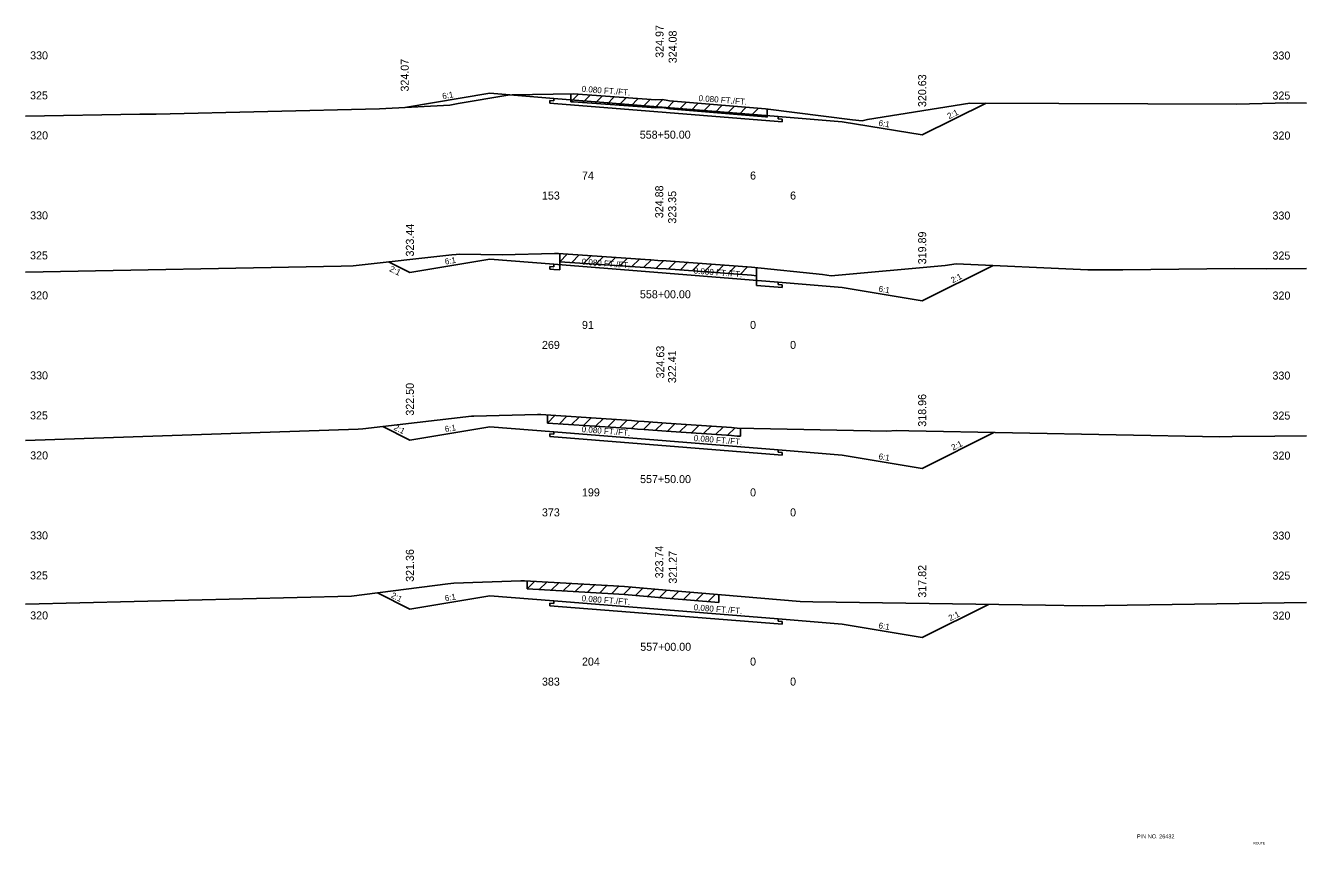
# Model space of a CAD drawing. Extents: x 2967 to 4323, y -3677 to -817.
# Drawn here: x 3555.3 to 3715.3, y -1162.9 to -1060.5 of the extents above; entities that cross this region are included whole.
import ezdxf

# ---------------------------------------------------------------- set-up
doc = ezdxf.new("R2010")
doc.units = 0
for name, color, linetype in [('Level 1', 7, 'Continuous'), ('Level 10', 7, 'Continuous'), ('Level 11', 7, 'Continuous'), ('Level 12', 7, 'Continuous'), ('Level 20', 7, 'Continuous'), ('Level 3', 7, 'Continuous'), ('Level 32', 7, 'Continuous'), ('Level 33', 7, 'Continuous'), ('Level 59', 7, 'Continuous'), ('Level 6', 7, 'Continuous'), ('Level 60', 7, 'Continuous'), ('Level 61', 7, 'Continuous'), ('Level 7', 7, 'Continuous')]:
    doc.layers.add(name, color=color, linetype=linetype)

msp = doc.modelspace()

# ---------------------------------------------------------------- linework, layer by layer
at = {"layer": 'Level 11'}
for p, q in [((3621.35, -1069.94), (3620.85, -1069.9)), ((3620.85, -1069.9), (3620.85, -1070.24)), ((3620.85, -1070.24), (3621.35, -1070.28)), ((3621.35, -1069.64), (3621.35, -1069.94)), ((3649.35, -1072.18), (3649.35, -1071.88)), ((3649.85, -1072.22), (3649.35, -1072.18)), ((3649.35, -1072.52), (3649.85, -1072.56)), ((3649.85, -1072.56), (3649.85, -1072.22)), ((3621.35, -1090.67), (3620.85, -1090.63)), ((3620.85, -1090.63), (3620.85, -1090.97)), ((3620.85, -1090.97), (3621.35, -1091.01)), ((3621.35, -1090.37), (3621.35, -1090.67)), ((3649.35, -1092.91), (3649.35, -1092.61)), ((3649.85, -1092.95), (3649.35, -1092.91)), ((3649.35, -1093.25), (3649.85, -1093.29)), ((3649.85, -1093.29), (3649.85, -1092.95)), ((3621.35, -1111.61), (3620.85, -1111.57)), ((3621.35, -1111.31), (3621.35, -1111.61)), ((3649.35, -1113.85), (3649.35, -1113.55)), ((3649.85, -1113.89), (3649.35, -1113.85)), ((3649.35, -1114.19), (3649.85, -1114.23)), ((3649.85, -1114.23), (3649.85, -1113.89)), ((3621.35, -1132.75), (3620.85, -1132.71)), ((3621.35, -1132.45), (3621.35, -1132.75)), ((3649.35, -1134.99), (3649.35, -1134.69)), ((3649.85, -1135.03), (3649.35, -1134.99)), ((3649.35, -1135.33), (3649.85, -1135.37)), ((3649.85, -1135.37), (3649.85, -1135.03))]:
    msp.add_line(p, q, dxfattribs=at)
at = {"layer": 'Level 12'}
for p, q in [((3635.35, -1071.4), (3621.35, -1070.28)), ((3635.35, -1071.4), (3649.35, -1072.52)), ((3622.08, -1089.05), (3622.08, -1091.07)), ((3622.08, -1091.07), (3621.35, -1091.01)), ((3646.64, -1090.81), (3646.64, -1093.04)), ((3646.64, -1093.04), (3649.35, -1093.25)), ((3620.85, -1111.57), (3620.85, -1111.91)), ((3620.85, -1111.91), (3649.35, -1114.19)), ((3620.85, -1132.71), (3620.85, -1133.05)), ((3620.85, -1133.05), (3649.35, -1135.33))]:
    msp.add_line(p, q, dxfattribs=at)
at = {"layer": 'Level 59'}
for p, q in [((3621.35, -1069.64), (3635.35, -1070.76)), ((3635.35, -1070.76), (3649.35, -1071.88)), ((3621.35, -1090.37), (3635.35, -1091.49)), ((3635.35, -1091.49), (3649.35, -1092.61)), ((3621.35, -1111.31), (3635.35, -1112.43)), ((3635.35, -1112.43), (3649.35, -1113.55)), ((3621.35, -1132.45), (3635.35, -1133.57)), ((3635.35, -1133.57), (3649.35, -1134.69))]:
    msp.add_line(p, q, dxfattribs=at)
at = {"layer": 'Level 6'}
for p, q in [((3613.35, -1069), (3621.35, -1069.64)), ((3649.35, -1071.88), (3657.35, -1072.55)), ((3613.35, -1089.73), (3621.35, -1090.37)), ((3649.35, -1092.61), (3657.35, -1093.28)), ((3613.35, -1110.67), (3621.35, -1111.31)), ((3649.35, -1113.55), (3657.35, -1114.22)), ((3613.35, -1131.81), (3621.35, -1132.45)), ((3649.35, -1134.69), (3657.35, -1135.36))]:
    msp.add_line(p, q, dxfattribs=at)
at = {"layer": 'Level 60'}
for p, q in [((3608.33, -1070.47), (3609.37, -1070.27)), ((3609.37, -1070.27), (3615.57, -1069.25)), ((3615.57, -1069.25), (3616.12, -1069.2)), ((3616.12, -1069.2), (3623.79, -1069.08)), ((3623.79, -1069.08), (3634.08, -1069.83)), ((3634.08, -1069.83), (3634.86, -1069.77)), ((3634.86, -1069.77), (3635.35, -1069.87)), ((3635.35, -1069.87), (3635.78, -1069.96)), ((3635.78, -1069.96), (3647.78, -1070.95)), ((3660.53, -1072.29), (3673.29, -1070.22)), ((3673.29, -1070.22), (3706.65, -1070.35)), ((3706.65, -1070.35), (3713.05, -1070.21)), ((3713.05, -1070.21), (3715.35, -1070.22)), ((3555.35, -1071.87), (3569.62, -1071.6)), ((3569.62, -1071.6), (3571.66, -1071.59)), ((3571.66, -1071.59), (3599.54, -1070.94)), ((3599.54, -1070.94), (3608.33, -1070.47)), ((3647.78, -1070.95), (3658.63, -1072.31)), ((3658.63, -1072.31), (3659.86, -1072.46)), ((3659.86, -1072.46), (3660.53, -1072.29)), ((3596.28, -1090.56), (3608.61, -1089.18)), ((3608.61, -1089.18), (3609.15, -1089.15)), ((3609.15, -1089.15), (3609.54, -1089.09)), ((3609.54, -1089.09), (3614.9, -1089.18)), ((3614.9, -1089.18), (3621.43, -1089.04)), ((3621.43, -1089.04), (3621.9, -1089.03)), ((3621.9, -1089.03), (3632.74, -1089.76)), ((3555.35, -1091.34), (3594.75, -1090.59)), ((3594.75, -1090.59), (3596.28, -1090.56)), ((3632.74, -1089.76), (3633.45, -1089.82)), ((3633.45, -1089.82), (3634.33, -1089.89)), ((3634.33, -1089.89), (3635.35, -1089.96)), ((3635.35, -1089.96), (3646.02, -1090.75)), ((3646.02, -1090.75), (3654.89, -1091.66)), ((3655.98, -1091.8), (3670.22, -1090.51)), ((3670.22, -1090.51), (3671.58, -1090.3)), ((3671.58, -1090.3), (3688.05, -1091.07)), ((3688.05, -1091.07), (3692.4, -1091.08)), ((3692.4, -1091.08), (3706.43, -1090.91)), ((3706.43, -1090.91), (3710.42, -1090.93)), ((3710.42, -1090.93), (3715.35, -1090.88)), ((3654.89, -1091.66), (3655.98, -1091.8)), ((3597.49, -1110.93), (3611.04, -1109.34)), ((3611.04, -1109.34), (3611.34, -1109.34)), ((3611.34, -1109.34), (3619.31, -1109.16)), ((3619.31, -1109.16), (3619.72, -1109.15)), ((3619.72, -1109.15), (3631.04, -1109.91)), ((3631.04, -1109.91), (3631.78, -1109.96)), ((3631.78, -1109.96), (3632.61, -1110.02)), ((3632.61, -1110.02), (3635.35, -1110.21)), ((3635.35, -1110.21), (3643.53, -1110.78)), ((3555.35, -1112.41), (3596.9, -1111)), ((3596.9, -1111), (3597.49, -1110.93)), ((3643.53, -1110.78), (3644.24, -1110.85)), ((3644.24, -1110.85), (3662.94, -1111.24)), ((3662.94, -1111.24), (3664.16, -1111.13)), ((3664.16, -1111.13), (3665.68, -1111.2)), ((3665.68, -1111.2), (3704.53, -1111.92)), ((3704.53, -1111.92), (3706.07, -1111.9)), ((3706.07, -1111.9), (3711.41, -1111.84)), ((3711.41, -1111.84), (3715.35, -1111.83)), ((3596.04, -1131.86), (3608.1, -1130.33)), ((3608.1, -1130.33), (3608.86, -1130.24)), ((3608.86, -1130.24), (3617.2, -1129.94)), ((3617.2, -1129.94), (3617.67, -1129.93)), ((3617.67, -1129.93), (3628.77, -1130.57)), ((3628.77, -1130.57), (3629.47, -1130.61)), ((3629.47, -1130.61), (3630.17, -1130.66)), ((3630.17, -1130.66), (3635.35, -1131.1)), ((3635.35, -1131.1), (3642.27, -1131.69)), ((3555.35, -1132.84), (3596.04, -1131.86)), ((3642.27, -1131.69), (3652.1, -1132.54)), ((3652.1, -1132.54), (3653.7, -1132.57)), ((3653.7, -1132.57), (3682.75, -1132.98)), ((3687.37, -1133.06), (3715.35, -1132.65)), ((3682.75, -1132.98), (3687.37, -1133.06))]:
    msp.add_line(p, q, dxfattribs=at)
at = {"layer": 'Level 61'}
for p, q in [((3623.44, -1069.08), (3623.44, -1070.08)), ((3624.4, -1069.12), (3623.44, -1070.08)), ((3623.44, -1070.08), (3623.79, -1070.08)), ((3623.79, -1070.08), (3634.08, -1070.83)), ((3625.87, -1069.23), (3624.94, -1070.16)), ((3627.37, -1069.34), (3626.44, -1070.27)), ((3628.87, -1069.45), (3627.94, -1070.38)), ((3630.37, -1069.56), (3629.44, -1070.49)), ((3631.87, -1069.67), (3630.94, -1070.6)), ((3633.37, -1069.78), (3632.44, -1070.71)), ((3634.96, -1069.79), (3633.94, -1070.82)), ((3636.32, -1070), (3635.44, -1070.89)), ((3637.86, -1070.13), (3636.94, -1071.05)), ((3639.36, -1070.25), (3638.44, -1071.18)), ((3640.86, -1070.38), (3639.94, -1071.3)), ((3634.08, -1070.83), (3634.86, -1070.77)), ((3634.86, -1070.77), (3635.35, -1070.87)), ((3635.35, -1070.87), (3635.78, -1070.96)), ((3635.78, -1070.96), (3647.78, -1071.95)), ((3642.36, -1070.5), (3641.44, -1071.43)), ((3643.86, -1070.63), (3642.94, -1071.55)), ((3645.36, -1070.75), (3644.44, -1071.68)), ((3646.86, -1070.88), (3645.94, -1071.8)), ((3647.78, -1071.95), (3648, -1071.98)), ((3648, -1071.98), (3648, -1070.98)), ((3622.08, -1089.05), (3622.08, -1090.05)), ((3623.02, -1089.11), (3622.08, -1090.05)), ((3624.52, -1089.21), (3623.58, -1090.15)), ((3626.02, -1089.31), (3625.08, -1090.25)), ((3627.52, -1089.41), (3626.59, -1090.35)), ((3629.03, -1089.51), (3628.09, -1090.45)), ((3622.08, -1090.05), (3632.74, -1090.76)), ((3630.53, -1089.61), (3629.59, -1090.55)), ((3632.03, -1089.72), (3631.09, -1090.65)), ((3633.53, -1089.82), (3632.59, -1090.75)), ((3632.74, -1090.76), (3633.45, -1090.82)), ((3633.45, -1090.82), (3634.33, -1090.89)), ((3635.03, -1089.94), (3634.1, -1090.87)), ((3634.33, -1090.89), (3635.35, -1090.96)), ((3635.35, -1090.96), (3646.02, -1091.75)), ((3636.53, -1090.05), (3635.6, -1090.98)), ((3638.03, -1090.16), (3637.1, -1091.09)), ((3639.54, -1090.27), (3638.6, -1091.2)), ((3641.04, -1090.38), (3640.11, -1091.31)), ((3642.54, -1090.49), (3641.61, -1091.42)), ((3644.04, -1090.6), (3643.11, -1091.53)), ((3645.54, -1090.71), (3644.61, -1091.65)), ((3646.64, -1091.81), (3646.64, -1090.81)), ((3646.02, -1091.75), (3646.64, -1091.81)), ((3620.54, -1109.21), (3620.54, -1110.21)), ((3621.48, -1109.27), (3620.54, -1110.21)), ((3620.54, -1110.21), (3631.04, -1110.91)), ((3622.98, -1109.37), (3622.04, -1110.31)), ((3624.48, -1109.47), (3623.54, -1110.41)), ((3625.98, -1109.57), (3625.05, -1110.51)), ((3627.48, -1109.67), (3626.55, -1110.61)), ((3628.98, -1109.77), (3628.05, -1110.71)), ((3630.48, -1109.87), (3629.55, -1110.81)), ((3631.98, -1109.98), (3631.05, -1110.91)), ((3633.48, -1110.08), (3632.55, -1111.02)), ((3634.98, -1110.19), (3634.05, -1111.12)), ((3636.48, -1110.29), (3635.55, -1111.23)), ((3637.98, -1110.39), (3637.05, -1111.33)), ((3631.04, -1110.91), (3631.78, -1110.96)), ((3631.78, -1110.96), (3632.61, -1111.02)), ((3632.61, -1111.02), (3635.35, -1111.21)), ((3635.35, -1111.21), (3643.53, -1111.78)), ((3639.48, -1110.5), (3638.55, -1111.43)), ((3640.98, -1110.6), (3640.05, -1111.54)), ((3642.49, -1110.71), (3641.55, -1111.64)), ((3643.97, -1110.82), (3643.05, -1111.74)), ((3643.53, -1111.78), (3644.24, -1111.85)), ((3644.24, -1111.85), (3644.67, -1111.86)), ((3644.67, -1111.86), (3644.67, -1110.86)), ((3617.99, -1129.95), (3617.99, -1130.95)), ((3618.94, -1130), (3617.99, -1130.95)), ((3617.99, -1130.95), (3628.77, -1131.57)), ((3620.45, -1130.09), (3619.5, -1131.03)), ((3621.95, -1130.17), (3621, -1131.12)), ((3623.46, -1130.26), (3622.51, -1131.2)), ((3624.96, -1130.35), (3624.01, -1131.29)), ((3626.46, -1130.43), (3625.52, -1131.38)), ((3627.97, -1130.52), (3627.02, -1131.46)), ((3629.47, -1130.61), (3628.52, -1131.55)), ((3630.96, -1130.73), (3630.03, -1131.65)), ((3632.46, -1130.86), (3631.53, -1131.78)), ((3633.96, -1130.98), (3633.04, -1131.9)), ((3635.47, -1131.11), (3634.54, -1132.03)), ((3628.77, -1131.57), (3629.47, -1131.61)), ((3629.47, -1131.61), (3630.17, -1131.66)), ((3630.17, -1131.66), (3635.35, -1132.1)), ((3635.35, -1132.1), (3641.93, -1132.66)), ((3636.97, -1131.24), (3636.05, -1132.16)), ((3638.47, -1131.37), (3637.55, -1132.29)), ((3639.98, -1131.5), (3639.06, -1132.42)), ((3641.48, -1131.63), (3640.56, -1132.55)), ((3641.93, -1132.66), (3641.93, -1131.66))]:
    msp.add_line(p, q, dxfattribs=at)
at = {"layer": 'Level 7'}
for p, q in [((3602.71, -1070.78), (3613.35, -1069)), ((3667.35, -1074.21), (3675.33, -1070.22)), ((3657.35, -1072.55), (3667.35, -1074.21)), ((3600.68, -1090.07), (3603.35, -1091.4)), ((3603.35, -1091.4), (3613.35, -1089.73)), ((3667.35, -1094.95), (3676.21, -1090.51)), ((3657.35, -1093.28), (3667.35, -1094.95)), ((3599.96, -1110.64), (3603.35, -1112.34)), ((3603.35, -1112.34), (3613.35, -1110.67)), ((3667.35, -1115.88), (3676.32, -1111.4)), ((3657.35, -1114.22), (3667.35, -1115.88)), ((3599.29, -1131.45), (3603.35, -1133.48)), ((3603.35, -1133.48), (3613.35, -1131.81)), ((3667.35, -1137.03), (3675.63, -1132.88)), ((3657.35, -1135.36), (3667.35, -1137.03))]:
    msp.add_line(p, q, dxfattribs=at)

# ---------------------------------------------------------------- texts
at = {"layer": 'Level 1'}
for s, p in [('74', (3624.85, -1079.78)), ('6', (3645.85, -1079.78)), ('153', (3619.85, -1082.28)), ('6', (3650.85, -1082.28)), ('91', (3624.85, -1098.45)), ('0', (3645.85, -1098.45)), ('269', (3619.85, -1100.95)), ('0', (3650.85, -1100.95)), ('199', (3624.85, -1119.38)), ('0', (3645.85, -1119.38)), ('373', (3619.85, -1121.88)), ('0', (3650.85, -1121.88)), ('204', (3624.85, -1140.53)), ('0', (3645.85, -1140.53)), ('383', (3619.85, -1143.03)), ('0', (3650.85, -1143.03))]:
    msp.add_text(s, height=1, dxfattribs=at).set_placement(p)
at = {"layer": 'Level 10'}
for s, p in [('324.97', (3635.04, -1064.56)), ('324.88', (3635, -1084.61)), ('324.63', (3635.13, -1104.64)), ('323.74', (3635, -1129.62))]:
    msp.add_text(s, height=1, rotation=90, dxfattribs=at).set_placement(p)
for s, p in [('558+50.00', (3632.07, -1074.67)), ('558+00.00', (3632.09, -1094.62)), ('557+50.00', (3632.11, -1117.72)), ('557+00.00', (3632.13, -1138.68))]:
    msp.add_text(s, height=1, dxfattribs=at).set_placement(p)
at = {"layer": 'Level 20'}
for s, height, p in [('PIN NO. 26432', 0.5, (3694.19, -1162.13)), ('ROUTE', 0.3, (3708.73, -1162.88))]:
    msp.add_text(s, height=height, dxfattribs=at).set_placement(p)
at = {"layer": 'Level 3'}
for s, p in [(' 330', (3555.54, -1064.76)), (' 330', (3710.74, -1064.78)), (' 325', (3555.53, -1069.76)), (' 325', (3710.74, -1069.78)), (' 320', (3555.55, -1074.76)), (' 320', (3710.75, -1074.78)), (' 330', (3555.54, -1084.76)), (' 330', (3710.74, -1084.78)), (' 325', (3555.53, -1089.76)), (' 325', (3710.74, -1089.78)), (' 320', (3555.55, -1094.76)), (' 320', (3710.75, -1094.78)), (' 330', (3555.54, -1104.76)), (' 330', (3710.74, -1104.78)), (' 325', (3555.53, -1109.76)), (' 325', (3710.74, -1109.78)), (' 320', (3555.55, -1114.76)), (' 320', (3710.75, -1114.78)), (' 330', (3555.54, -1124.76)), (' 330', (3710.74, -1124.78)), (' 325', (3555.53, -1129.76)), (' 325', (3710.74, -1129.78)), (' 320', (3555.55, -1134.76)), (' 320', (3710.75, -1134.78))]:
    msp.add_text(s, height=1, dxfattribs=at).set_placement(p)
at = {"layer": 'Level 32'}
for s, rotation, p in [('6:1', 9.4623, (3607.46, -1069.73)), ('0.080 FT./FT.', 355.4261, (3624.79, -1068.8)), ('0.080 FT./FT.', 355.4261, (3639.39, -1069.96)), ('2:1', 26.5651, (3670.72, -1072.25)), ('6:1', 350.5377, (3661.86, -1073.05)), ('6:1', 9.4623, (3607.78, -1090.41)), ('2:1', 333.435, (3600.72, -1091.19)), ('0.080 FT./FT.', 355.4261, (3624.79, -1090.4)), ('0.080 FT./FT.', 355.4261, (3638.79, -1091.52)), ('2:1', 26.5651, (3671.16, -1092.76)), ('6:1', 350.5377, (3661.86, -1093.78)), ('2:1', 333.435, (3601.26, -1111.01)), ('6:1', 9.4623, (3607.78, -1111.35)), ('0.080 FT./FT.', 355.4261, (3624.79, -1111.34)), ('0.080 FT./FT.', 355.4261, (3638.79, -1112.46)), ('2:1', 26.5651, (3671.22, -1113.67)), ('6:1', 350.5377, (3661.86, -1114.72)), ('2:1', 333.435, (3600.92, -1131.99)), ('6:1', 9.4623, (3607.78, -1132.49)), ('0.080 FT./FT.', 355.4261, (3624.79, -1132.48)), ('0.080 FT./FT.', 355.4261, (3638.79, -1133.6)), ('2:1', 26.5651, (3670.87, -1134.98)), ('6:1', 350.5377, (3661.86, -1135.86))]:
    msp.add_text(s, height=0.75, rotation=rotation, dxfattribs=at).set_placement(p)
at = {"layer": 'Level 33'}
for s, p in [('324.07', (3603.21, -1068.78)), ('320.63', (3667.85, -1070.72)), ('323.44', (3603.85, -1089.4)), ('319.89', (3667.85, -1090.37)), ('322.50', (3603.85, -1109.29)), ('318.96', (3667.85, -1110.67)), ('321.36', (3603.85, -1130.06)), ('317.82', (3667.85, -1132.04))]:
    msp.add_text(s, height=1, rotation=90, dxfattribs=at).set_placement(p)
at = {"layer": 'Level 59'}
for s, p in [(' 324.08', (3636.68, -1065.62)), (' 323.35', (3636.62, -1085.66)), (' 322.41', (3636.61, -1105.6)), (' 321.27', (3636.7, -1130.66))]:
    msp.add_text(s, height=1, rotation=90, dxfattribs=at).set_placement(p)

doc.saveas('drawing.dxf')
